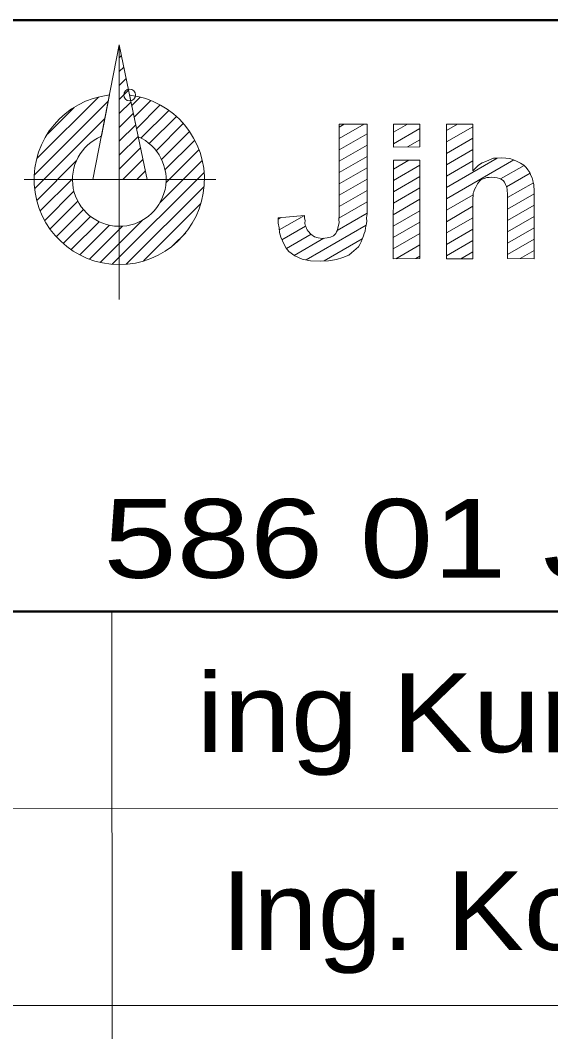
# Model space of a CAD drawing. Extents: x -670514 to -669423, y -1130798 to -1130123.
# Drawn here: x -669761.35 to -669755.96, y -1130749.79 to -1130739.52 of the extents above; entities that cross this region are included whole.
import ezdxf
from ezdxf.enums import TextEntityAlignment as Align

# ---------------------------------------------------------------- set-up
doc = ezdxf.new("R2010")
doc.units = 0
doc.header["$LTSCALE"] = 0.24
doc.header["$PDMODE"] = 32
doc.header["$PDSIZE"] = 0.12
doc.layers.add('61', color=7, linetype='Continuous', lineweight=13)

msp = doc.modelspace()

# ---------------------------------------------------------------- linework, layer by layer
at = {"layer": '61'}
for p, q in [((-669760.608, -1130741.142), (-669760.342, -1130739.776)), ((-669760.341, -1130740.666), (-669760.342, -1130739.776)), ((-669760.341, -1130739.906), (-669760.319, -1130739.884)), ((-669760.341, -1130740.047), (-669760.295, -1130740.001)), ((-669760.341, -1130740.188), (-669760.271, -1130740.118)), ((-669760.341, -1130740.33), (-669760.247, -1130740.235)), ((-669761.178, -1130740.93), (-669760.553, -1130740.305)), ((-669760.441, -1130740.284), (-669760.523, -1130740.703)), ((-669760.15, -1130740.707), (-669760.236, -1130740.284)), ((-669760.214, -1130740.391), (-669760.129, -1130740.305)), ((-669760.19, -1130740.508), (-669760.022, -1130740.34)), ((-669761.203, -1130741.097), (-669760.453, -1130740.347)), ((-669761.071, -1130740.682), (-669760.8, -1130740.411)), ((-669760.341, -1130740.471), (-669760.222, -1130740.353)), ((-669760.166, -1130740.626), (-669759.925, -1130740.385)), ((-669760.121, -1130740.722), (-669759.839, -1130740.44)), ((-669761.199, -1130741.234), (-669760.488, -1130740.523)), ((-669760.341, -1130740.613), (-669760.198, -1130740.47)), ((-669760.036, -1130740.778), (-669759.761, -1130740.503)), ((-669760.341, -1130740.754), (-669760.174, -1130740.587)), ((-669759.967, -1130740.851), (-669759.691, -1130740.575)), ((-669758.108, -1130740.724), (-669757.857, -1130740.579)), ((-669758.108, -1130740.609), (-669758.058, -1130740.58)), ((-669757.559, -1130740.779), (-669757.292, -1130740.624)), ((-669757.558, -1130740.663), (-669757.415, -1130740.58)), ((-669757.022, -1130740.646), (-669756.908, -1130740.58)), ((-669757.022, -1130740.761), (-669756.753, -1130740.606)), ((-669760.53, -1130740.707), (-669760.522, -1130740.699)), ((-669760.341, -1130742.361), (-669760.341, -1130740.666)), ((-669760.341, -1130740.896), (-669760.15, -1130740.705)), ((-669759.913, -1130740.938), (-669759.629, -1130740.654)), ((-669759.877, -1130741.043), (-669759.575, -1130740.742)), ((-669758.108, -1130740.84), (-669757.827, -1130740.677)), ((-669757.416, -1130740.811), (-669757.291, -1130740.74)), ((-669757.022, -1130740.877), (-669756.753, -1130740.721)), ((-669760.341, -1130741.037), (-669760.126, -1130740.822)), ((-669759.868, -1130741.176), (-669759.532, -1130740.84)), ((-669758.108, -1130740.955), (-669757.827, -1130740.793)), ((-669757.022, -1130740.992), (-669756.753, -1130740.837)), ((-669761.178, -1130741.355), (-669760.777, -1130740.953)), ((-669760.305, -1130741.142), (-669760.101, -1130740.939)), ((-669759.931, -1130741.38), (-669759.5, -1130740.949)), ((-669758.109, -1130741.071), (-669757.827, -1130740.908)), ((-669757.559, -1130741.037), (-669757.401, -1130740.945)), ((-669757.022, -1130741.223), (-669756.506, -1130740.925)), ((-669757.022, -1130741.339), (-669756.337, -1130740.943)), ((-669757.022, -1130741.108), (-669756.753, -1130740.952)), ((-669760.164, -1130741.143), (-669760.077, -1130741.056)), ((-669758.109, -1130741.186), (-669757.826, -1130741.023)), ((-669757.559, -1130741.152), (-669757.29, -1130740.997)), ((-669756.472, -1130741.136), (-669756.233, -1130740.999)), ((-669761.305, -1130741.142), (-669760.608, -1130741.142)), ((-669761.143, -1130741.461), (-669760.816, -1130741.134)), ((-669760.608, -1130741.142), (-669760.341, -1130741.142)), ((-669760.412, -1130742.002), (-669759.481, -1130741.071)), ((-669760.06, -1130741.143), (-669759.361, -1130741.142)), ((-669758.109, -1130741.302), (-669757.826, -1130741.139)), ((-669757.559, -1130741.268), (-669757.29, -1130741.112)), ((-669756.411, -1130741.217), (-669756.173, -1130741.079)), ((-669761.098, -1130741.557), (-669760.801, -1130741.26)), ((-669760.27, -1130742.002), (-669759.48, -1130741.212)), ((-669758.109, -1130741.417), (-669757.826, -1130741.254)), ((-669757.559, -1130741.383), (-669757.29, -1130741.228)), ((-669756.4, -1130741.326), (-669756.139, -1130741.175)), ((-669761.043, -1130741.644), (-669760.761, -1130741.362)), ((-669758.112, -1130741.534), (-669757.826, -1130741.369)), ((-669757.56, -1130741.499), (-669757.29, -1130741.343)), ((-669757.022, -1130741.454), (-669756.75, -1130741.297)), ((-669756.402, -1130741.442), (-669756.131, -1130741.286)), ((-669760.98, -1130741.723), (-669760.704, -1130741.447)), ((-669760.096, -1130741.969), (-669759.512, -1130741.386)), ((-669757.56, -1130741.614), (-669757.291, -1130741.459)), ((-669757.022, -1130741.57), (-669756.752, -1130741.414)), ((-669756.401, -1130741.558), (-669756.132, -1130741.402)), ((-669760.909, -1130741.793), (-669760.633, -1130741.516)), ((-669760.829, -1130741.854), (-669760.545, -1130741.57)), ((-669760.534, -1130741.983), (-669760.103, -1130741.552)), ((-669758.729, -1130741.545), (-669758.703, -1130741.529)), ((-669758.717, -1130741.653), (-669758.463, -1130741.506)), ((-669758.13, -1130741.66), (-669757.826, -1130741.485)), ((-669757.56, -1130741.73), (-669757.291, -1130741.574)), ((-669757.022, -1130741.685), (-669756.754, -1130741.53)), ((-669756.401, -1130741.673), (-669756.132, -1130741.518)), ((-669760.74, -1130741.907), (-669760.439, -1130741.606)), ((-669760.643, -1130741.951), (-669760.307, -1130741.615)), ((-669758.691, -1130741.753), (-669758.45, -1130741.614)), ((-669758.445, -1130741.958), (-669757.836, -1130741.606)), ((-669757.022, -1130741.801), (-669756.754, -1130741.646)), ((-669756.401, -1130741.788), (-669756.132, -1130741.633)), ((-669759.797, -1130741.812), (-669759.667, -1130741.682)), ((-669758.644, -1130741.842), (-669758.395, -1130741.698)), ((-669758.566, -1130741.912), (-669758.265, -1130741.739)), ((-669758.263, -1130741.968), (-669757.875, -1130741.744)), ((-669757.56, -1130741.845), (-669757.291, -1130741.69)), ((-669757.022, -1130741.916), (-669756.753, -1130741.761)), ((-669756.4, -1130741.903), (-669756.132, -1130741.749)), ((-669757.534, -1130741.946), (-669757.291, -1130741.805)), ((-669756.875, -1130741.946), (-669756.753, -1130741.876)), ((-669756.273, -1130741.945), (-669756.132, -1130741.864)), ((-669757.333, -1130741.945), (-669757.291, -1130741.921)), ((-669760.416, -1130745.524), (-669760.412, -1130759.527)), ((-669770.416, -1130747.528), (-669750.412, -1130747.525)), ((-669770.41, -1130749.527), (-669750.414, -1130749.526))]:
    msp.add_line(p, q, dxfattribs=at)
at = {"layer": '61', "lineweight": 53}
msp.add_line((-669770.413, -1130745.528), (-669750.416, -1130745.525), dxfattribs=at)
msp.add_lwpolyline([(-669810.41, -1130759.541), (-669750.413, -1130759.522), (-669750.414, -1130739.525), (-669810.413, -1130739.537)], close=True, dxfattribs=at)
at = {"layer": '61'}
for points in [[(-669760.15, -1130740.705), (-669760.059, -1130741.143), (-669760.341, -1130741.142), (-669760.341, -1130739.776)], [(-669757.559, -1130740.812), (-669757.291, -1130740.811), (-669757.292, -1130740.58), (-669757.558, -1130740.58)], [(-669757.29, -1130740.945), (-669757.559, -1130740.946), (-669757.56, -1130741.946), (-669757.291, -1130741.945)]]:
    msp.add_lwpolyline(points, close=True, dxfattribs=at)
for points in [[(-669757.827, -1130740.579), (-669757.826, -1130741.446), (-669757.826, -1130741.491), (-669757.831, -1130741.53), (-669757.83, -1130741.567), (-669757.835, -1130741.604), (-669757.844, -1130741.633), (-669757.847, -1130741.667), (-669757.856, -1130741.689), (-669757.864, -1130741.714), (-669757.876, -1130741.746), (-669757.888, -1130741.774), (-669757.899, -1130741.801), (-669757.915, -1130741.824), (-669757.937, -1130741.847), (-669757.96, -1130741.867), (-669757.985, -1130741.888), (-669758.01, -1130741.909), (-669758.071, -1130741.935), (-669758.136, -1130741.955), (-669758.217, -1130741.966), (-669758.303, -1130741.97), (-669758.399, -1130741.966), (-669758.486, -1130741.95), (-669758.559, -1130741.918), (-669758.619, -1130741.872), (-669758.646, -1130741.84), (-669758.669, -1130741.803), (-669758.686, -1130741.766), (-669758.701, -1130741.727), (-669758.714, -1130741.681), (-669758.72, -1130741.632), (-669758.73, -1130741.585), (-669758.729, -1130741.532), (-669758.462, -1130741.506), (-669758.46, -1130741.534), (-669758.456, -1130741.559), (-669758.457, -1130741.584), (-669758.454, -1130741.605), (-669758.446, -1130741.625)], [(-669758.446, -1130741.625), (-669758.44, -1130741.639), (-669758.433, -1130741.653), (-669758.425, -1130741.665), (-669758.397, -1130741.697), (-669758.36, -1130741.723), (-669758.324, -1130741.734), (-669758.278, -1130741.74), (-669758.233, -1130741.735), (-669758.197, -1130741.726), (-669758.167, -1130741.714), (-669758.145, -1130741.69), (-669758.137, -1130741.672), (-669758.128, -1130741.657), (-669758.123, -1130741.632), (-669758.116, -1130741.608), (-669758.111, -1130741.58), (-669758.113, -1130741.548), (-669758.109, -1130741.51), (-669758.109, -1130741.47), (-669758.108, -1130740.58), (-669757.827, -1130740.579)], [(-669757.022, -1130741.947), (-669757.022, -1130740.58), (-669756.753, -1130740.58), (-669756.753, -1130741.055), (-669756.726, -1130741.027), (-669756.694, -1130740.998), (-669756.657, -1130740.973), (-669756.62, -1130740.958), (-669756.583, -1130740.941), (-669756.543, -1130740.927), (-669756.502, -1130740.925), (-669756.462, -1130740.921), (-669756.417, -1130740.925), (-669756.376, -1130740.929), (-669756.339, -1130740.942), (-669756.303, -1130740.958), (-669756.269, -1130740.977), (-669756.237, -1130740.995), (-669756.213, -1130741.019), (-669756.194, -1130741.043), (-669756.176, -1130741.072), (-669756.165, -1130741.1), (-669756.152, -1130741.124), (-669756.143, -1130741.153), (-669756.14, -1130741.173), (-669756.134, -1130741.194), (-669756.135, -1130741.218), (-669756.131, -1130741.241), (-669756.132, -1130741.27), (-669756.131, -1130741.298), (-669756.131, -1130741.327), (-669756.132, -1130741.359), (-669756.132, -1130741.946), (-669756.4, -1130741.945), (-669756.402, -1130741.408), (-669756.4, -1130741.372), (-669756.4, -1130741.34), (-669756.4, -1130741.312), (-669756.4, -1130741.282), (-669756.404, -1130741.26)], [(-669756.404, -1130741.26), (-669756.404, -1130741.242), (-669756.408, -1130741.224), (-669756.413, -1130741.212), (-669756.421, -1130741.191), (-669756.432, -1130741.169), (-669756.445, -1130741.152), (-669756.461, -1130741.141), (-669756.482, -1130741.132), (-669756.506, -1130741.125), (-669756.53, -1130741.12), (-669756.56, -1130741.117), (-669756.586, -1130741.12), (-669756.612, -1130741.123), (-669756.639, -1130741.132), (-669756.667, -1130741.141), (-669756.685, -1130741.16), (-669756.705, -1130741.185), (-669756.722, -1130741.219), (-669756.741, -1130741.25), (-669756.744, -1130741.266), (-669756.749, -1130741.282), (-669756.75, -1130741.307), (-669756.753, -1130741.331), (-669756.754, -1130741.355), (-669756.753, -1130741.385), (-669756.752, -1130741.413), (-669756.754, -1130741.446), (-669756.753, -1130741.946), (-669757.022, -1130741.947)]]:
    msp.add_lwpolyline(points, dxfattribs=at)
for radius, start, end in [(0.864, 96.63837, 83.05228), (0.475, 112.46724, 66.22789)]:
    msp.add_arc((-669760.341, -1130741.142), radius, start, end, dxfattribs=at)
msp.add_point((-669760.236, -1130740.284), dxfattribs=at)

# ---------------------------------------------------------------- texts
for s, rotation, width, p in [('586 01 JIHLAVA ', 0.013, 1.25, (-669755.3736, -1130745.1848)), ('ing Kuropata', 359.935, 1.15, (-669756.0685, -1130746.9563))]:
    msp.add_text(s, height=0.8, rotation=rotation, dxfattribs=dict(at, width=width)).set_placement(p, align=Align.CENTER)
at = {"layer": '61', "width": 1.1}
msp.add_text('Ing. Koubek', height=0.8, rotation=0.015, dxfattribs=at).set_placement((-669759.309, -1130748.965))

doc.saveas('drawing.dxf')
